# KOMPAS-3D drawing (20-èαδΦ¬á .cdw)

Views: Вид 1
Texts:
  Крышка
  Андрей
  Noncommercial version
  Ra3.2
  Ra6.3
  Ra12,5
  Уклоны формовочные по ГОСТ 3212-80.
  Необработанные внутренние поверхности покрыть грунтовкой.
  СЧ15 ГОСТ 1412-85
  ТФ ДГТУ
  кафедра ТМс
  ОКМА-30.06.01.00.15-
Dimensions and other numbers on the sheet: 120; 150; 100; 40; 22; 1,5; 20; 0,02; 135; 6 отв.; 13; 0,8; 4; 1:1; 1; 0,4; 0; 2; 3; 5; 6; 7; 8; 9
